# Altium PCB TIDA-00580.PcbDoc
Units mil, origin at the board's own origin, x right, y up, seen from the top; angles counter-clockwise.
Board outline 2640 x 3160 mil, 4 copper layers (Top, Ground, Power, Bottom), stack 38.234 mil thick; 68 components, 61 nets, 219 pads, 95 vias.
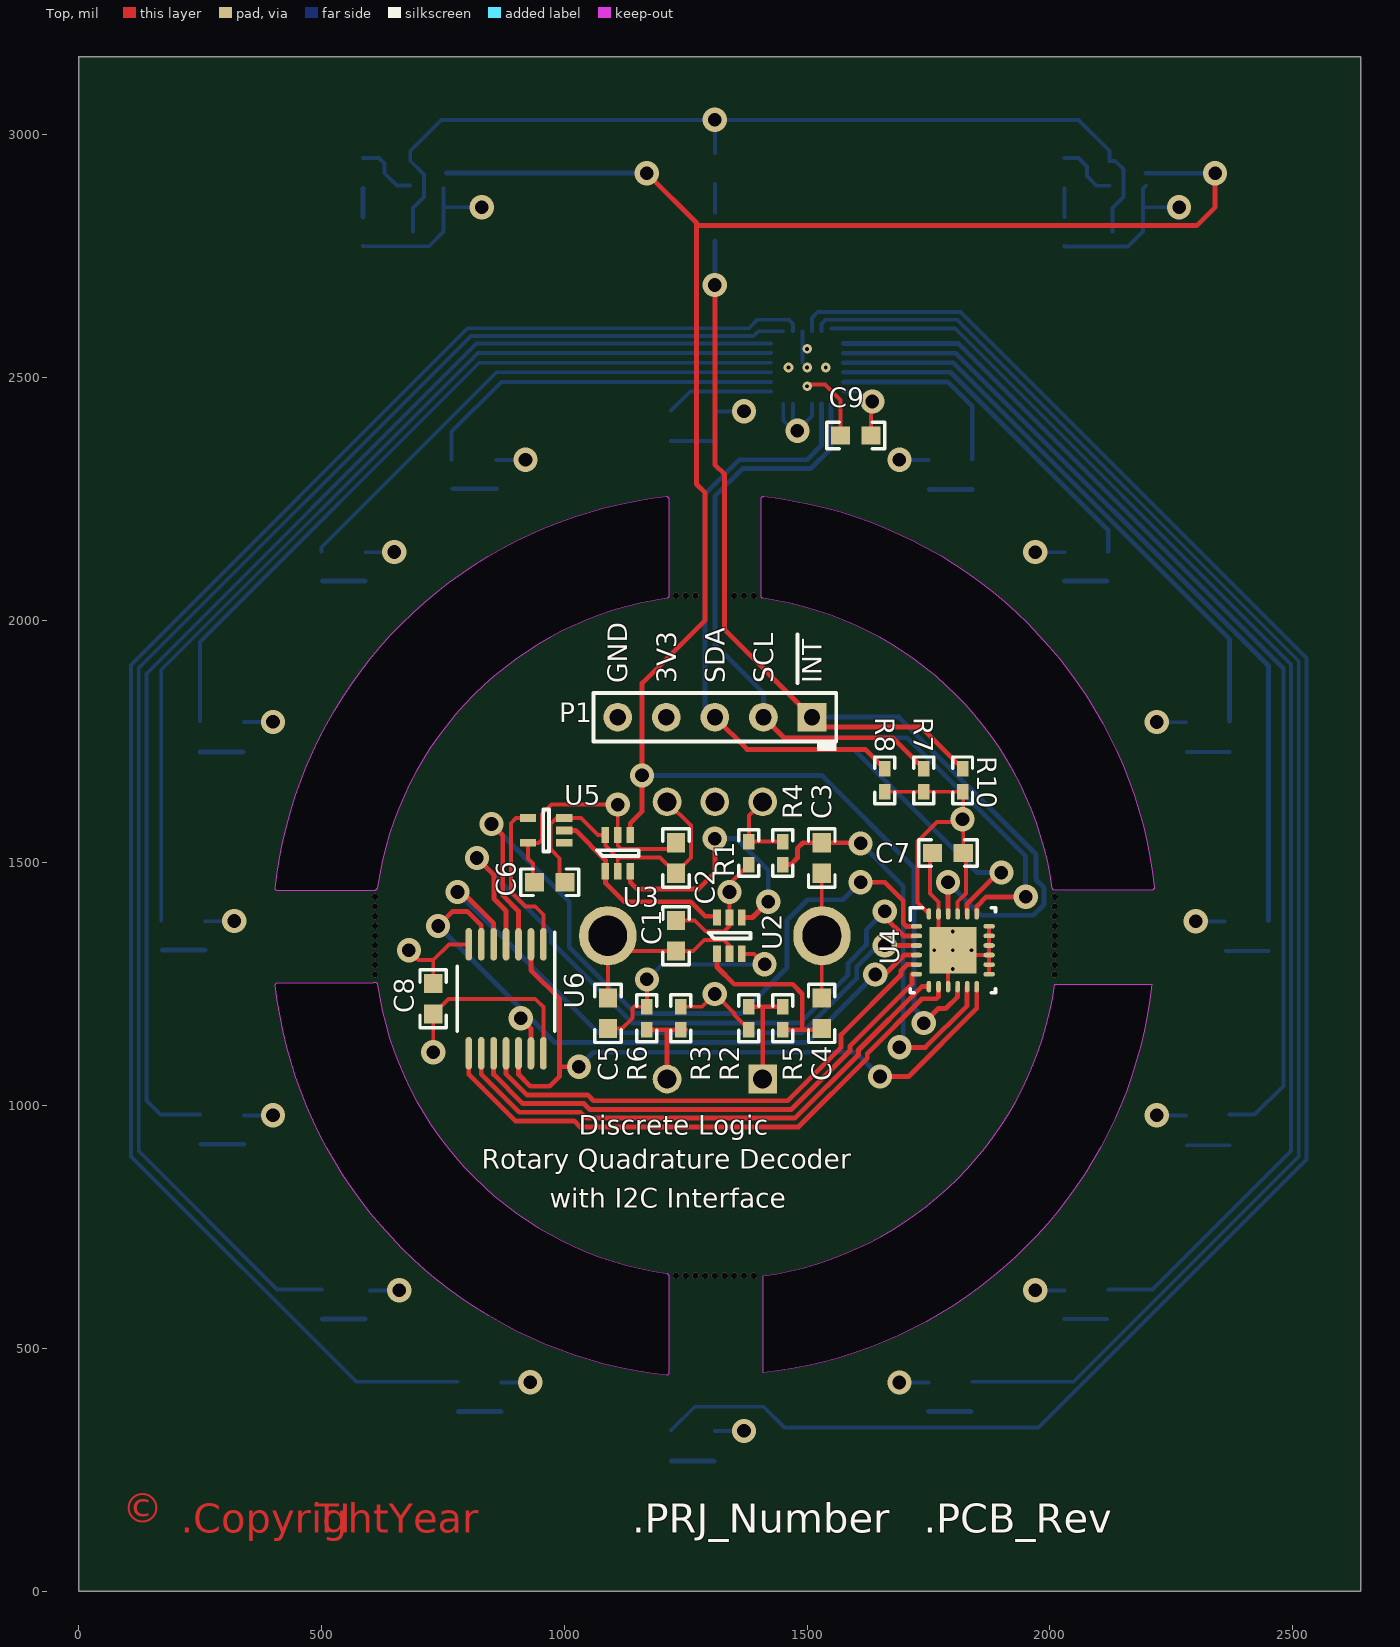
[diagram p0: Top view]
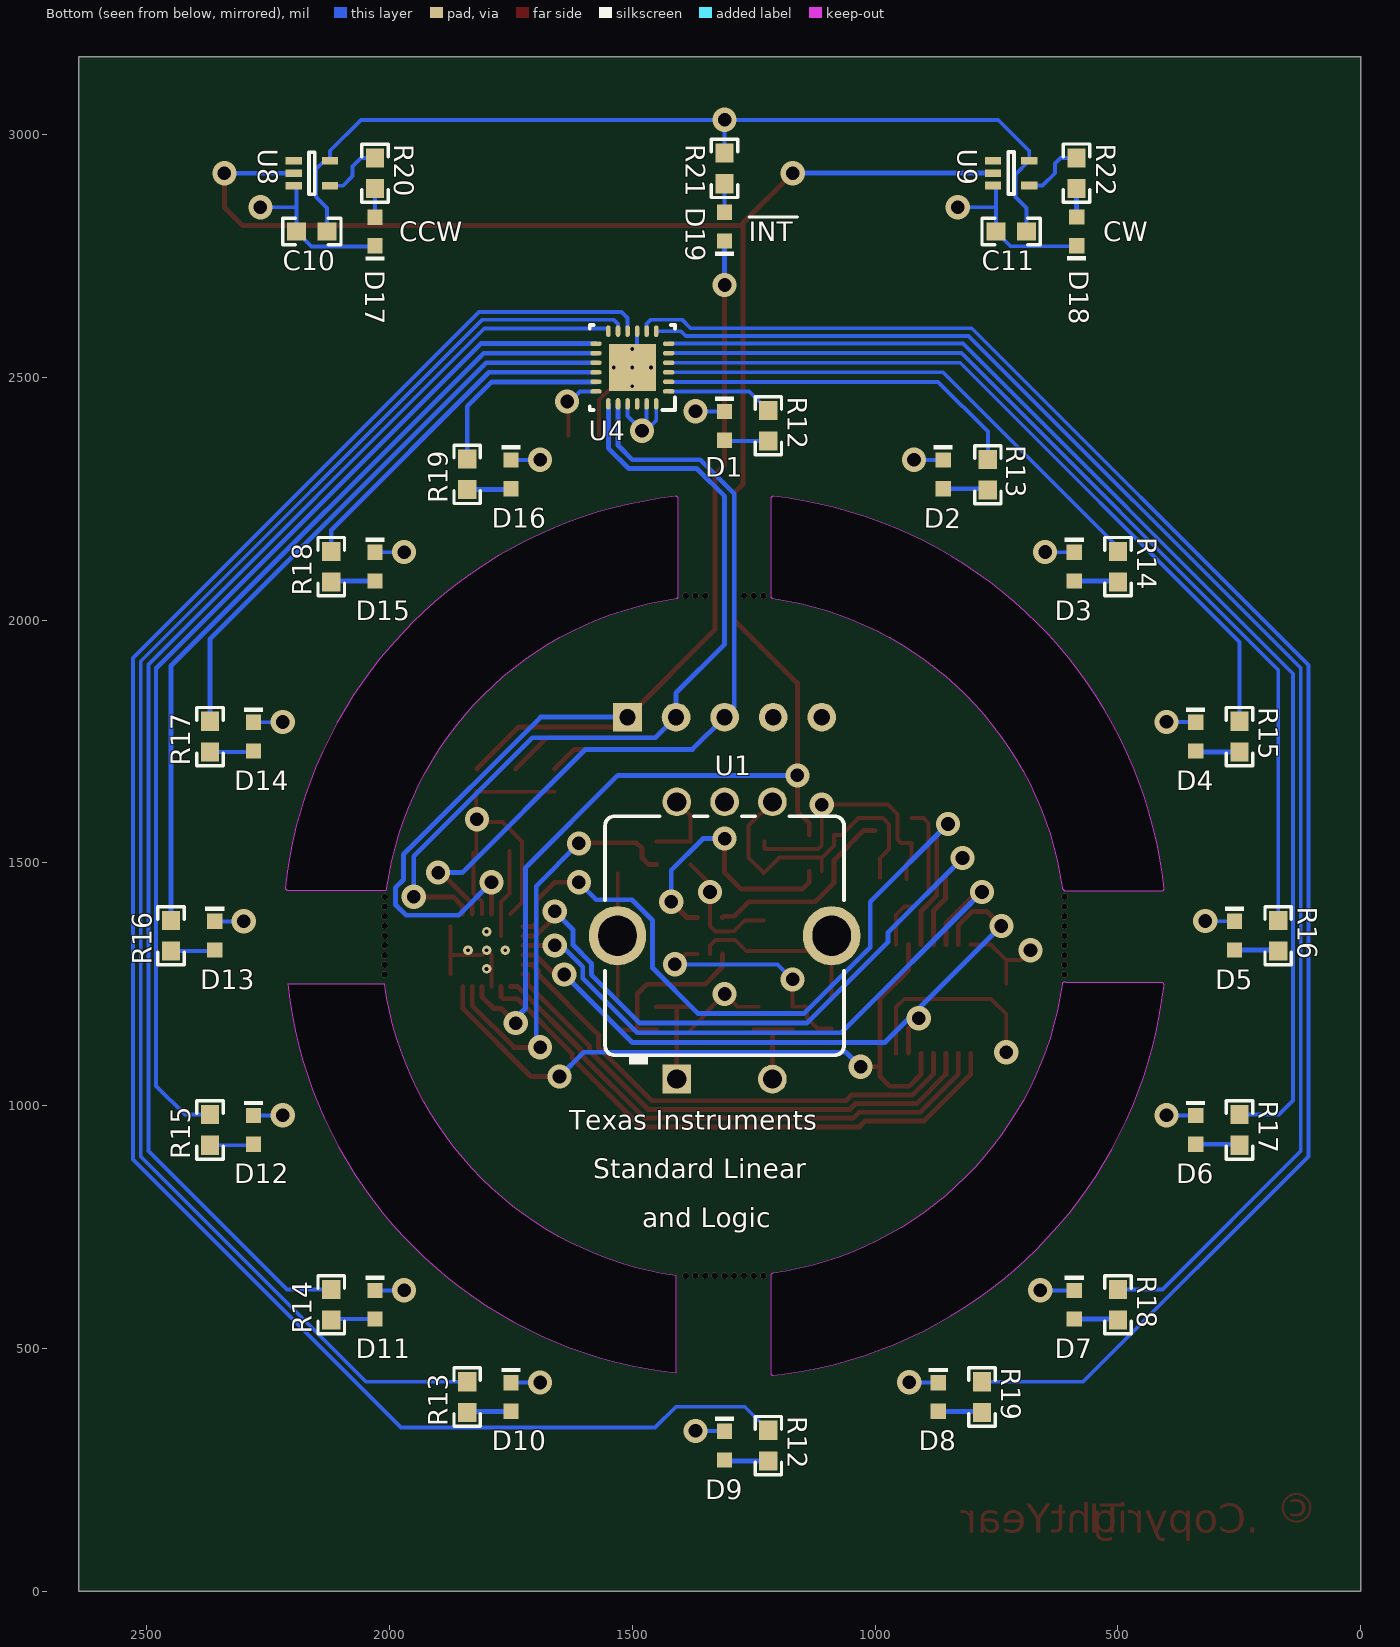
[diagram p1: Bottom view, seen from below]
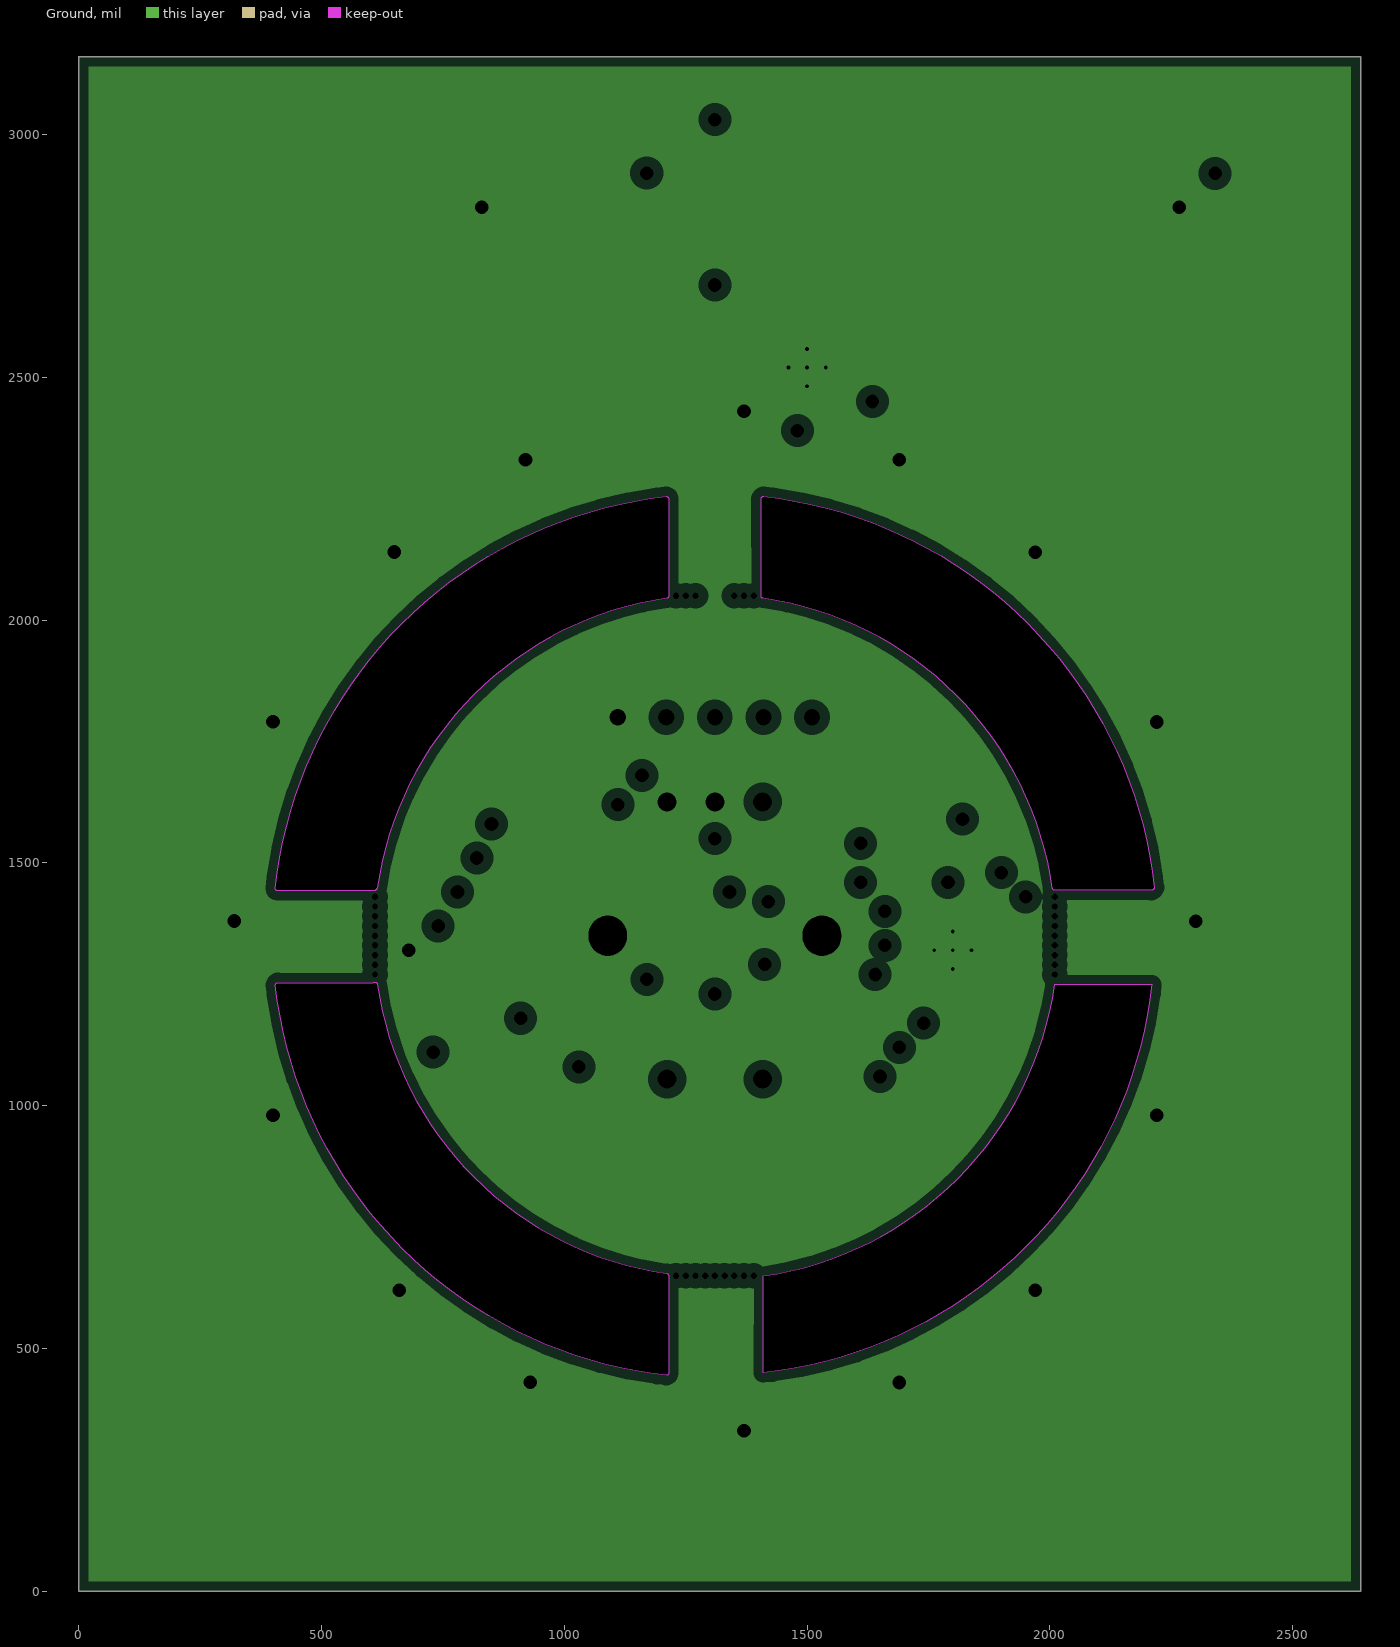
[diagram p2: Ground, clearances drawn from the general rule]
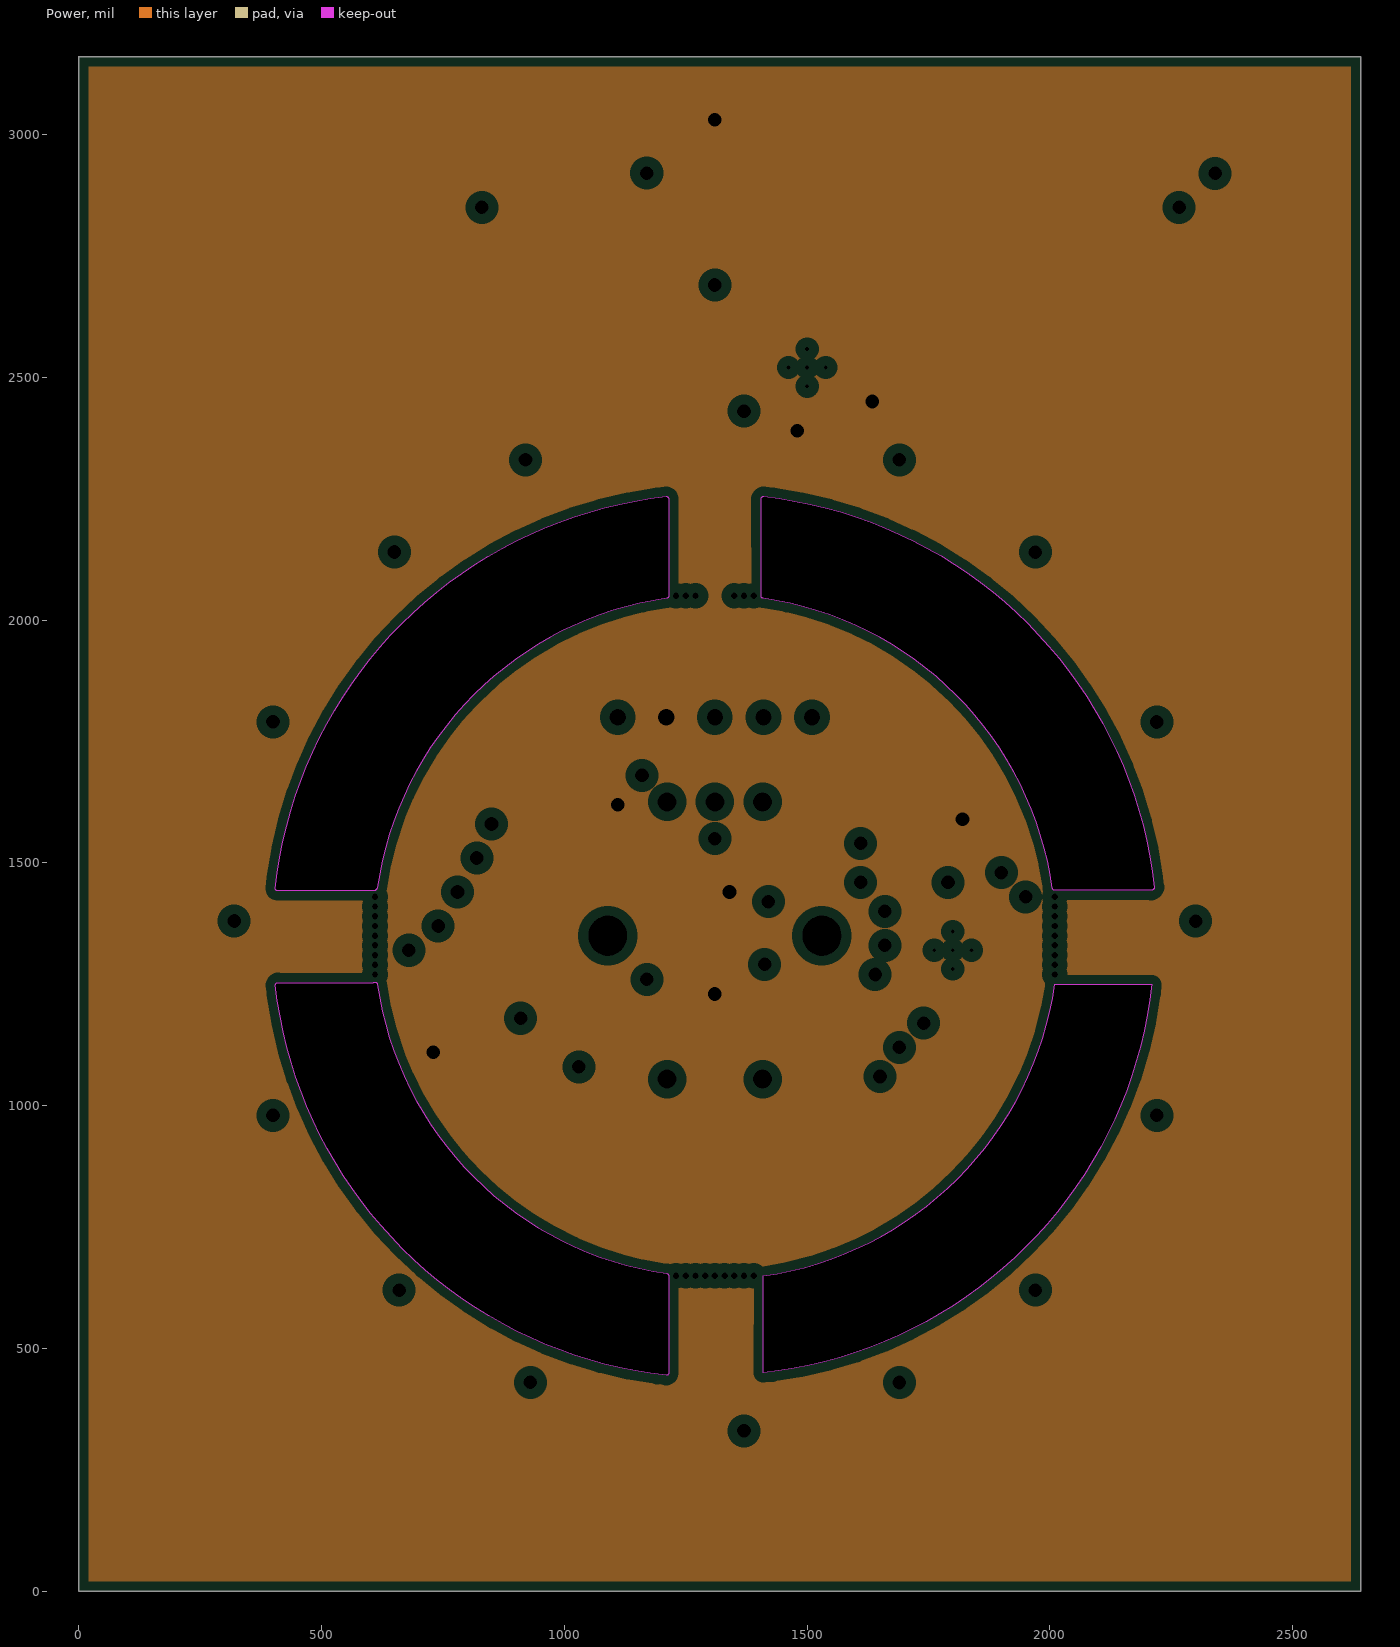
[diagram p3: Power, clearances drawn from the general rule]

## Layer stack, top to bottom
Top Solder: solder mask 0.4, Solder Resist, Dk 3.5
Top: signal copper 1.4
Dielectric 1: core 12.6, FR-4, Dk 4.8
Ground: plane copper 1.417, net GND
Dielectric 3: core 10, Dk 4.2
Power: plane copper 1.417, net 3V3
Dielectric 4: core 10, Dk 4.2
Bottom: signal copper 1.4
Bottom Solder: solder mask 0.4, Solder Resist, Dk 3.5

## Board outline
0,0 0,3160 2640,3160 2640,0 0,0
cut-out: 1409.32,2044.56 cw(c1410,2049.53) 1404.98,2049.53 1404.98,2249.53 cw(c1410,2249.53) 1410.55,2254.52 cw(c1310,1349.53) 2214.98,1450.08 cw(c2210,1449.53) 2215.01,1449.53 cw(c2210,1449.53) 2212.78,1445.36 cw(c2208.62,1448.15) 2208.62,1443.14 2010.19,1443.14 cw(c2010.19,1448.15) 2005.22,1447.48 cw(c1310.2,1349.45) 2005.23,1447.45 2005.22,1447.48 ccw(c1310,1349.53)
cut-out: 409.76,1442.37 cw(c409.76,1447.38) 404.78,1447.92 cw(c1310,1349.53) 1209.44,2254.52 cw(c1210,2249.53) 1215.01,2249.53 1215.01,2049.53 cw(c1210,2049.53) 1210.67,2044.56 cw(c1308.58,1350.43) 1210.71,2044.57 1210.67,2044.56 ccw(c1310,1349.53) 614.96,1448.82 cw(c610,1449.53) 612.3,1445.08 cw(c607.85,1447.38) 607.85,1442.37
cut-out: 405.14,1247.86 cw(c410.12,1248.42) 410.12,1253.44 606.85,1253.44 cw(c610,1249.53) 614.96,1250.24 ccw(c1310,1349.53) 1210.67,654.5 ccw(c1308.58,1348.64) 1210.71,654.5 1210.67,654.5 cw(c1210,649.53) 1215.01,649.53 1215.01,449.53 cw(c1210,449.53) 1209.44,444.55 cw(c1310,1349.53)
cut-out: 1410,449.53 1410,649.53 ccw(c1310,1349.53) 2010,1249.53 2210,1249.53 cw(c1310,1349.53)

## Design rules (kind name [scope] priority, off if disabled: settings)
AcuteAngle [All] p1: minimum=4.50000000000000E+0001 checktracksonly=FALSE
AssemblyTestPointUsage [All] p1: valid=2
Clearance Clearance_Keepouts [((IsTrack Or IsArc) And Not InPoly) And IsFree and IsKeepOut vs ((IsTrack Or IsArc) And Not InPoly) And IsFree and IsKeepOut] p1: gap=0
Clearance Clearance_BoardEdge_MountingHoles [OnCopper and InComponentClass('Mounting Holes') vs IsKeepOut] p2: gap=40
Clearance Clearance_BoardEdge_Poly [OnCopper and InPoly vs IsKeepOut] p3: gap=25
Clearance Clearance_BoardEdge [OnCopper and Not InComponentClass('Logo') and not InComponentClass('FiducialMark') and not InRegion(1000,500,4000,800) and Not IsKeepout vs IsKeepOut] p4: gap=75
Clearance Clearance_Poly [InPolygon] p5: gap=25
Clearance [All] p6: gap=7.87
ComponentClearance ComponentClearance_MountingHoles_FiducialMarks [InComponentClass('Mounting Holes') vs InComponentClass('FiducialMark')] p1: gap=50 collisioncheckmode=3 verticalgap=10 showdistances=FALSE
ComponentClearance ComponentClearance_Shunt [InComponentClass('Header') vs InComponentClass('Shunt')] p2: gap=0 collisioncheckmode=3 verticalgap=0 showdistances=FALSE
ComponentClearance ComponentClearance_Logo [InComponentClass('Logo')] p3: gap=50 collisioncheckmode=3 verticalgap=10 showdistances=FALSE
ComponentClearance ComponentClearance_ScrewToNut [(HasFootprint('NY PMS 440 0025 PH')) vs (HasFootprint('Keystone_1902C'))] p4: gap=5 collisioncheckmode=3 verticalgap=10 showdistances=FALSE
ComponentClearance ComponentClearance_MountingHoles [InComponentClass('Mounting Holes')] p5: gap=250 collisioncheckmode=3 verticalgap=100000 showdistances=FALSE
ComponentClearance ComponentClearance_SmallPassives [HasFootprint('0201*') or HasFootprint('0402*') or HasFootprint('0508') or HasFootprint('0603*') or HasFootprint('0612') or HasFootprint('0805*') or HasFootprint('0815*') or HasFootprint('0830*') or HasFootprint('1206*') or HasFootprint('1210*') or HasFootprint('1808*') or HasFootprint('1812*') or HasFootprint('1825*') or HasFootprint('2010*') or HasFootprint('2220*') or HasFootprint('2225*') or HasFootprint('2512*') or HasFootprint('2728*') or HasFootprint('3518*') vs HasFootprint('0201*') or HasFootprint('0402*') or HasFootprint('0508') or HasFootprint('0603*') or HasFootprint('0612') or HasFootprint('0805*') or HasFootprint('0815*') or HasFootprint('0830*') or HasFootprint('1206*') or HasFootprint('1210*') or HasFootprint('1808*') or HasFootprint('1812*') or HasFootprint('1825*') or HasFootprint('2010*') or HasFootprint('2220*') or HasFootprint('2225*') or HasFootprint('2512*') or HasFootprint('2728*') or HasFootprint('3518*')] p6: gap=20 collisioncheckmode=3 verticalgap=10 showdistances=FALSE
ComponentClearance ComponentClearance_THtoSMT [IsThruComponent vs IsSMTComponent] p7: gap=25 collisioncheckmode=3 verticalgap=30 showdistances=FALSE
ComponentClearance ComponentClearance_THtoTH [IsThruComponent vs IsThruComponent] p8: gap=25 collisioncheckmode=3 verticalgap=30 showdistances=FALSE
ComponentClearance [All] p9: gap=25 collisioncheckmode=3 verticalgap=10 showdistances=FALSE
DiffPairsRouting [All] p1: maxlimit=100 minlimit=10 mostfreqgap=10 toplayer_minwidth=15 toplayer_maxwidth=15 toplayer_prefwidth=15 bottomlayer_minwidth=15 bottomlayer_maxwidth=15 bottomlayer_prefwidth=15 maxuncoupledlength=1000
FabricationTestPointUsage TestPointUsage [All] p1: valid=2 allowmultiple=FALSE
FabricationTestpoint Testpoint [All] p1: side=3 testpointundercomponent=TRUE minsize=40 maxsize=100 preferedsize=60 minholesize=0 maxholesize=40 preferedholesize=32 testpointgrid=1 allowsidetop=TRUE allowsidebottom=TRUE usegrid=TRUE gridtolerance=0.01
FanoutControl Fanout_LCC [IsLCC] p1: bgadir=Out bgaviamode=Centered fanoutstyle=Auto fanoutdirection=Alternating viagrid=1 // Fanout_LCC (Default Rule)
FanoutControl Fanout_BGA [IsBGA] p2: bgadir=Out bgaviamode=Centered fanoutstyle=Auto fanoutdirection=Alternating viagrid=1 // Fanout_BGA (Default Rule)
FanoutControl Fanout_Default [All] p4: bgadir=Out bgaviamode=Centered fanoutstyle=Auto fanoutdirection=Alternating viagrid=1 // Fanout_Default (Default Rule)
FanoutControl Fanout_Small [(CompPinCount < 5)] p5: bgadir=Out bgaviamode=Centered fanoutstyle=Auto fanoutdirection=OutThenIn viagrid=1 // Fanout_Small (Default Rule)
HoleSize [All] p1: absolutevalues=TRUE maxlimit=251 minlimit=8 maxpercent=80.000 minpercent=20.000
MinimumAnnularRing MinimumAnnularRing_ThermalPadVias [IsVia and InAnyComponent] p1: minimumring=5.91
MinimumAnnularRing [All] p2: minimumring=9
MinimumSolderMaskSliver MinimumSolderMaskSliver_Logo [InComponentClass('Logo') vs InComponentClass('Logo')] p1: minsoldermaskwidth=0.7
MinimumSolderMaskSliver [All] p2: minsoldermaskwidth=3.94
PlaneClearance [All] p1: clearance=20
PlaneConnect [All] p1: planeconnectstyle=Relief reliefexpansion=10 reliefentries=4 reliefconductorwidth=10 reliefairgap=10
PolygonConnect [All] p1: connectstyle=Relief reliefconductorwidth=10 reliefentries=4 polygonreliefangle="90 Angle" airgapwidth=10
RoutingVias ThermalPadVias [IsVia and InAnyComponent] p1: holewidth=7.87 width=19.68 viastyle="Through Hole" minholewidth=7.87 minwidth=19.68 maxholewidth=12.99 maxwidth=23.62
RoutingVias [All] p2: holewidth=13 width=34 viastyle="Through Hole" minholewidth=13 minwidth=20 maxholewidth=40 maxwidth=65
SilkToBoardRegionClearance [Not ((IsComment or IsDesignator) And (Hide <> 'False')) and not InRegion(1000,500,4000,800)] p1:
SilkToSilkClearance SilkToSilkClearance_Pb-FreeLogo [(HasFootprint('Pb-Free_Overlay_Medium') OR HasFootprint('Pb-Free_Overlay_Small')) vs (HasFootprint('Pb-Free_Overlay_Medium') OR HasFootprint('Pb-Free_Overlay_Small'))] p1: silktosilkclearance=0
SilkToSilkClearance [All] p2: silktosilkclearance=5
SilkToSolderMaskClearance "Silk to Solder Mask Opening" [All] p1: minsilkscreentomaskgap=1 clearancetoexposedcopper=FALSE
SolderMaskExpansion [All] p1: expansion=1.97
UnpouredPolygon [All] p1: allowunpoured=FALSE
Width [All] p1: maxlimit=100 minlimit=6 preferedwidth=10 checkconnectedcopper=TRUE
13 further rules are at their usual default settings.

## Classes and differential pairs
component class "Test Interface": C9 C10 C11 D1 D2 D3 D4 D5 D6 D7 D8 D9 D10 D11 D12 D13 D14 D15 D16 D17 D18 D19 R12 R13 R14 R15 R16 R17 R18 R19 R20 R21 R22 U4 U8 U9
component class TIDA-00580_Schematic: 3V3 C1 C2 C3 C4 C5 C6 C7 C8 P1 R1 R2 R3 R4 R5 R6 R7 R8 R10 U1 U2 U3 U4 U5 U6
component class Header: P1

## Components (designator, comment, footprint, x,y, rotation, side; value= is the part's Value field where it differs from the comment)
C1 "0603YC104JAT2A" 0603 1230,1350 r270 top
C2 "0603YC104JAT2A" 0603 1230,1510 r270 top
C3 "0603YC104JAT2A" 0603 1530,1510 r270 top
C4 "0603YC104JAT2A" 0603 1530,1190 r90 top
C5 "0603YC104JAT2A" 0603 1090,1190 r90 top
C6 "0603YC104JAT2A" 0603 970,1460 r0 top
C7 "0603YC104JAT2A" 0603 1790,1520 r180 top
C8 "0603YC104JAT2A" 0603 730,1220 r90 top
C9 "0603YC104JAT2A" 0603 1600,2380 r180 top
C10 "0603YC104JAT2A" 0603 2160,2800 r0 bottom
C11 "0603YC104JAT2A" 0603 720,2800.32 r0 bottom
D1 "LB Q39G-L2N2-35-1" "LB Q39G_BLUE" 1310,2400 r90 bottom
D2 "LB Q39G-L2N2-35-1" "LB Q39G_BLUE" 860,2300 r90 bottom
D3 "LB Q39G-L2N2-35-1" "LB Q39G_BLUE" 590,2110 r90 bottom
D4 "LB Q39G-L2N2-35-1" "LB Q39G_BLUE" 340,1760 r90 bottom
D5 "LB Q39G-L2N2-35-1" "LB Q39G_BLUE" 260,1350 r90 bottom
D6 "LB Q39G-L2N2-35-1" "LB Q39G_BLUE" 340,950 r90 bottom
D7 "LB Q39G-L2N2-35-1" "LB Q39G_BLUE" 590,590 r90 bottom
D8 "LB Q39G-L2N2-35-1" "LB Q39G_BLUE" 870,400 r90 bottom
D9 "LB Q39G-L2N2-35-1" "LB Q39G_BLUE" 1310,300 r90 bottom
D10 "LB Q39G-L2N2-35-1" "LB Q39G_BLUE" 1750,400 r90 bottom
D11 "LB Q39G-L2N2-35-1" "LB Q39G_BLUE" 2030,590 r90 bottom
D12 "LB Q39G-L2N2-35-1" "LB Q39G_BLUE" 2280,950 r90 bottom
D13 "LB Q39G-L2N2-35-1" "LB Q39G_BLUE" 2359.99,1350 r90 bottom
D14 "LB Q39G-L2N2-35-1" "LB Q39G_BLUE" 2280,1760 r90 bottom
D15 "LB Q39G-L2N2-35-1" "LB Q39G_BLUE" 2030,2110 r90 bottom
D16 "LB Q39G-L2N2-35-1" "LB Q39G_BLUE" 1750,2300 r90 bottom
D17 "LB Q39G-L2N2-35-1" "LB Q39G_BLUE" 2030,2800 r270 bottom
D18 "LB Q39G-L2N2-35-1" "LB Q39G_BLUE" 585.11,2800.32 r270 bottom
D19 "LB Q39G-L2N2-35-1" "LB Q39G_BLUE" 1310,2810 r270 bottom
P1 "800-10-005-10-001000" Mill-Max_800-10-005-10-001000 1310,1800 r180 top
R1 "CRCW04021K00FKED" 0402 1380,1520 r270 top
R2 "CRCW04021K00FKED" 0402 1380,1180 r270 top
R3 "CRCW04021K00FKED" 0402 1240,1180 r90 top
R4 "CRCW04021K00FKED" 0402 1450,1520 r90 top
R5 "CRCW04021K00FKED" 0402 1450,1180 r90 top
R6 "CRCW04021K00FKED" 0402 1170,1180 r270 top
R7 "CRCW04024K70JNED" 0402 1740,1670 r270 top
R8 "CRCW04024K70JNED" 0402 1660,1670 r270 top
R10 "CRCW040210K0JNED" 0402 1820,1670 r270 top
R12 "CRCW0603100RJNEA" 0603 1220,300 r90 bottom
R12 "CRCW0603100RJNEA" 0603 1220,2400 r90 bottom
R13 "CRCW0603100RJNEA" 0603 1840,400 r90 bottom
R13 "CRCW0603100RJNEA" 0603 767.95,2299.1 r90 bottom
R14 "CRCW0603100RJNEA" 0603 2120,590 r90 bottom
R14 "CRCW0603100RJNEA" 0603 500,2110 r90 bottom
R15 "CRCW0603100RJNEA" 0603 2370,950 r90 bottom
R15 "CRCW0603100RJNEA" 0603 250,1760 r90 bottom
R16 "CRCW0603100RJNEA" 0603 2450,1350 r90 bottom
R16 "CRCW0603100RJNEA" 0603 170,1350 r90 bottom
R17 "CRCW0603100RJNEA" 0603 2370,1760 r90 bottom
R17 "CRCW0603100RJNEA" 0603 250,950 r90 bottom
R18 "CRCW0603100RJNEA" 0603 2120,2110 r90 bottom
R18 "CRCW0603100RJNEA" 0603 500,590 r90 bottom
R19 "CRCW0603100RJNEA" 0603 1840,2300 r90 bottom
R19 "CRCW0603100RJNEA" 0603 780,400 r90 bottom
R20 "CRCW0603100RJNEA" 0603 2030,2920 r90 bottom
R21 "CRCW0603100RJNEA" 0603 1310,2930 r90 bottom
R22 "CRCW0603100RJNEA" 0603 585.11,2920.32 r90 bottom
U1 "EVE-JBBF2020B" Panasonic_EVE-JBBF2020B 1310,1350 r90 bottom
U2 "SN74LVC2G17QDCKRQ1" DCK0006A_N 1340,1350 r90 top
U3 "SN74LVC1G374DCKR" DCK0006A_N 1110,1520 r90 top
U4 "TCA9539RTWR" RTW0024B 1800,1320 r0 top
U4 "TCA9539RTWR" RTW0024B 1500,2520 r0 bottom
U5 "SN74LVC1G04QDCKRQ1" DCK0005A_N 962.4,1566.73 r180 top
U6 "SN74LV393ATPWRQ1" PW0014A_N 880,1220 r270 top
U8 "SN74LV1T34DCKR" DCK0005A_N 2160,2920 r180 bottom
U9 "SN74LV1T04DCK" DCK0005A_N 720,2920.32 r180 bottom

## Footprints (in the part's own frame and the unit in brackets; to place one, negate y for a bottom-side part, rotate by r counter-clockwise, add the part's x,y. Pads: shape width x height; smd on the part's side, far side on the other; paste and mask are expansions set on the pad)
0402 [mm] "0402 from SM-752 data"
  rect 0.8x0.6 smd: 1(-0.6,0) 2(0.6,0)
  silkscreen extent -1.22,-0.52 1.22,0.52, body extent -0.55,-0.3 0.55,0.3, height 0.6
0603 [mm] "0603 from SM-752 data"
  rect 1x0.95 smd: 1(-0.8,0) 2(0.8,0)
  silkscreen extent -1.52,-0.69 1.52,0.69, body extent -0.87,-0.47 0.87,0.47, height 0.85
DCK0005A_N [mm] "SOT353, 5-Leads, Body 2x1.3mm, Pitch 0.65mm, Lead Span 2.1mm, IPC Medium Density"
  rect 0.85x0.4 smd: 1(-0.95,0.65) 2(-0.95,0) 3(-0.95,-0.65) 4(0.95,-0.65) 5(0.95,0.65)
  silkscreen extent -0.15,-1.1 0.15,1.1, body extent -1.14,-1 1.14,1, height 0.94
DCK0006A_N [mm] "SOT23, 6-Leads, Body 2x1.3mm, Pitch 0.65mm, Lead Span 2.1mm, IPC Medium Density"
  rect 0.85x0.4 smd: 1(-0.95,0.65) 2(-0.95,0) 3(-0.95,-0.65) 4(0.95,-0.65) 5(0.95,0) 6(0.95,0.65)
  silkscreen extent -0.15,-1.1 0.15,1.1, body extent -1.14,-1 1.14,1, height 0.94
"LB Q39G_BLUE" [mm] "OSRAM"
  rect 0.8x0.8 smd: 1(-0.75,0) 2(0.75,0)
  silkscreen extent 1.3,-0.5 1.52,0.5, body extent -0.85,-0.45 0.85,0.45, height 0.4
Mill-Max_800-10-005-10-001000 [mm] "Mill-Max"
  rect 1.5x1.5 hole 0.85: 1(-5.08,0)
  round 1.5 hole 0.85: 2(-2.54,0) 3(0,0) 4(2.54,0) 5(5.08,0)
  silkscreen extent -6.35,-1.27 6.35,1.78, body extent -6.35,-1.27 6.35,1.27, height 8.13
Panasonic_EVE-JBBF2020B [mm] "TH, 5-Leads, Body 12.4x12.4mm, Pitch 2.5mm"
  rect 1.5x1.5 hole 1: 1(-7.5,2.5)
  round 1.5 hole 1: 2(-7.5,-2.5) 3(7,2.5) 4(7,0) 5(7,-2.5)
  oval 3.1x3 hole 2 slot 2.1 at 0 deg: 6(0,5.6) 7(0,-5.6)
  silkscreen extent -6.75,-6.25 6.25,6.25, body extent -7.6,-6.7 7.1,6.7, height 20.1
PW0014A_N [mm] "TSOP, 14-Leads, Body 5x4.4mm, Pitch 0.65mm, IPC Medium Density"
  oval 1.7x0.35 smd: 1(-2.85,1.95) 2(-2.85,1.3) 3(-2.85,0.65) 4(-2.85,0) 5(-2.85,-0.65) 6(-2.85,-1.3) 7(-2.85,-1.95) 8(2.85,-1.95) 9(2.85,-1.3) 10(2.85,-0.65) 11(2.85,0) 12(2.85,0.65) 13(2.85,1.3) 14(2.85,1.95)
  silkscreen extent -3.47,-2.55 1.7,2.55, body extent -3.21,-2.5 3.21,2.5, height 0.98
RTW0024B [mm] "QFN, 24-Leads, Body 4x4mm, Pitch 0.5mm, Thermal Pad 2.45x2.45mm, TI Recommended"
  oval 0.6x0.24 smd: 1(-1.9,1.25) 2(-1.9,0.75) 3(-1.9,0.25) 4(-1.9,-0.25) 5(-1.9,-0.75) 6(-1.9,-1.25) 13(1.9,-1.25) 14(1.9,-0.75) 15(1.9,-0.25) 16(1.9,0.25) 17(1.9,0.75) 18(1.9,1.25)
  oval 0.24x0.6 smd: 7(-1.25,-1.9) 8(-0.75,-1.9) 9(-0.25,-1.9) 10(0.25,-1.9) 11(0.75,-1.9) 12(1.25,-1.9) 19(1.25,1.9) 20(0.75,1.9) 21(0.25,1.9) 22(-0.25,1.9) 23(-0.75,1.9) 24(-1.25,1.9)
  rect 2.45x2.45 smd paste-1.225: 25(0,0)
  silkscreen extent -2.22,-2.22 2.22,2.22, body extent -2.07,-2.07 2.07,2.07, height 0.81

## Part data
C1 C2 C3 C4 C5 C6 C7 C8 C9 C10 C11: "CAP, CERM, 0.1 µF, 16 V, +/- 5%, X7R, 0603"
D1 D2 D3 D4 D5 D6 D7 D8 D9 D10 D11 D12 D13 D14 D15 D16 D17 D18 D19: "LED, Blue, SMD"
P1: "Header, 100mil, 5x1, TH"
R1 R2 R3 R4 R5 R6: "RES, 1.00 k, 1%, 0.063 W, 0402"
R7 R8: "RES, 4.7 k, 5%, 0.063 W, 0402"
R10: "RES, 10 k, 5%, 0.063 W, 0402"
R12 R12 R13 R13 R14 R14 R15 R15 R16 R16 R17 R17 R18 R18 R19 R19 R20 R21 R22: "RES, 100, 5%, 0.1 W, 0603"
U1: "ENCODER ROTARY 12MM 20PPR W/SW, TH"
U2: "Dual Schmitt Trigger Buffer, DCK0006A"
U3: "Single D-Type Flip-Flop With 3-State Output, DCK0006A"
U4 U4: "Remote 16-Bit I2C and SMBus, Low-Power I/O Expander with Interrupt Output, Reset & Config. Register, 1.65 to 5.5 V, -40 to 85 degC, 24-pin QFN (RTW), Green (RoHS & no Sb/Br)"
U5: library part SN74LVC1G04DCKR, "Single Inverter Gate, DCK0005A"
U6: "DUAL 4-BIT BINARY COUNTER, PW0014A"
U8: "Single Power Supply Single Buffer GATE CMOS Logic Level Shifter, DCK0005A"
U9: "SN74LV1T04 Single Power Supply Inverter Gate CMOS Logic Level Shifter, DCK0005A"

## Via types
v1: diameter 50, hole 28, Top to Bottom, 52 vias
v2: diameter 13, hole 13, Top to Bottom, 33 vias
v3: diameter 19.68, hole 7.87, Top to Bottom, 10 vias

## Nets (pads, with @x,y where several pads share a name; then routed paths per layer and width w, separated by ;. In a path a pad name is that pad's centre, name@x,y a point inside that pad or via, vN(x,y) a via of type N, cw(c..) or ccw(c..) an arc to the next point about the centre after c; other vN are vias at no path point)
3V3: C1.1 C2.1 C6.1 C7.1 C8.1 C9.1 C10.1 C11.1 P1.4 R1.2 R2.2 R3.2 R7.2 R8.2 R10.2 R21.2 U2.5 U3.5 U4.18@1574.8,2470.79 U4.21 U4.23@1470.47,2445.2 U4.24 U5.5 U6.14 U8.5 U9.5 | length 4368.6
  Top w8: v1(730,1110) C8.1 761.5,1220 940,1220 956.77,1203.23 U6.14 ; C6.1@935.57,1466.73 935.57,1498.76 925,1509.33 U5.5 946.81,1541.14 953.61,1547.94 953.61,1600 973.61,1620 v1(1110,1620) U3.5 1110,1535.91 1117.11,1528.8 1227.16,1528.8 1227.5,1529.13 C2.1@1227.5,1544 ; C1.1 1268.5,1381.5 1290.92,1359.08 1300,1359.08 1300.28,1358.8 1329.11,1358.8 1340,1369.69 U2.5 1340,1456.38 R1.2 ; R3.2 1283.62,1203.62 v1(1310,1230) 1350,1190 1350,1186.38 R2.2 ; C9.1 v1@1631.5,2447.08 ; R8.2 R10.2 ; U4.24@1750.79,1394.8 1726.95,1418.65 1726.95,1543.62 1767.58,1584.25 v1@1821.5,1584.25 ; U4.21@1809.84,1394.8 1809.84,1419.84 1826.87,1436.87 C7.1@1826.87,1520 ; C7.1 v1@1821.5,1584.25 ; R10.2@1821.5,1648.5 v1@1821.5,1584.25
  Bottom w8: C11.1 688.5,2848.82 711.2,2871.52 711.2,2917.3 U9.5 682.6,2966.06 746.54,3030 v1@1310,3030 ; v1@1305.91,3030 2059.06,3030 2122.6,2966.46 U8.5 2134.41,2945.59 2151.2,2928.8 2151.2,2871.21 2128.5,2848.5 C10.1 ; R21.2 v1(1310,3030.47) ; U4.24@1450.79,2445.2 1450.79,2410.79 v1@1471.57,2390 ; v1@1470.47,2399.53 U4.23@1470.47,2445.2 ; v1(1480,2390) 1509.84,2419.84 U4.21@1509.84,2445.2 ; U4.18@1574.8,2470.79 1608.05,2470.79 1628.84,2450 v1(1634.42,2450)
  other v1: 1340,1440 1820,1590
\INT\: D19.2 P1.1 R10.1 U4.22@1790.16,1394.8 | length 2406.2
  Top w10: v1(1310,2690) 1310,2320 1330,2300 1330,1980 P1.1 1530,1780 1733.62,1780 R10.1 ; v1(1790,1460) 1790,1394.96 U4.22@1790.16,1394.8
  Bottom w10: v1(1310,2690) D19.2 ; P1.1 1688.84,1800 1971.2,1517.64 1971.2,1465.49 1987.87,1448.82 1987.87,1414.31 1965.69,1392.13 1857.87,1392.13 v1(1790,1460)
A: C4.1 R5.1 U2.1 | length 377.1
  Top w10: U2.1 1314.41,1285.59 1350,1250 1470,1250 1490,1230 1490,1156.38 ; R5.1 1490,1156.38 ; C4.1@1527.87,1156.38 1490,1156.38
A_BUF: U2.6 U3.1 U5.2 | length 416.3
  Top w10: U5.2 1023.27,1566.73 1084.41,1505.59 U3.1 1084.41,1458.81 1123.22,1420 1260,1420 1290,1390 1311.81,1390 U2.6
A_NOT: U5.4 U6.1 | length 328.2
  Top w8: U5.4 900.75,1592.32 890,1581.58 890,1440 920,1410 940,1410 956.77,1393.23 U6.1
B: C5.1 R6.1 U2.3 | length 478.7
  Top w8: C5.1 1118.5,1158.5 1140,1180 1140,1200 1145,1205 1146.38,1203.62 R6.1 v1(1170,1260) ; U2.3 1390.63,1312.6 v1(1412.29,1290.95)
  Bottom w8: v1(1170,1260) 1200.94,1290.95 v1(1412.29,1290.95)
B_BUF: U2.4 U3.3 | length 556.2
  Top w10: U3.3 1135.59,1460.43 1150.08,1445.95 1275.94,1445.95 1310,1480 v1(1310,1550) ; U2.4 1387.4,1387.4 v1(1420,1420)
  Bottom w10: v1(1310,1550) 1354.5,1550 1420,1484.5 v1(1420,1420)
COUNT0: U4.1@1725.2,1369.21 U6.3 | length 1596.8
  Top w10: v1(850,1580) 873.13,1556.87 873.13,1433.01 905.59,1400.55 U6.3 ; v1(1610,1460) 1660,1460 1697.87,1422.13 1697.87,1375.7 1704.36,1369.21 U4.1@1725.2,1369.21
  Bottom w10: v1(850,1580) 1010,1420 1010,1325.84 1145.84,1190 1364.9,1190 1458.54,1283.64 1458.54,1381.76 1500.68,1423.9 1573.9,1423.9 v1(1610,1460)
COUNT1: U4.2@1725.2,1349.53 U6.4 | length 1415.2
  Top w10: v1(820,1510) 855.25,1474.75 855.25,1425.61 880,1400.86 U6.4 ; v1(1660,1400) 1660,1388.29 1698.77,1349.53 U4.2@1725.2,1349.53
  Bottom w10: v1(820,1510) 973.19,1356.81 973.19,1337.37 1140.56,1170 1484.72,1170 1584.25,1269.53 1584.25,1293.09 1622.13,1330.97 1622.13,1362.13 v1(1660,1400)
COUNT2: U4.3@1725.2,1329.84 U6.5 | length 1274.7
  Top w10: v1@790,1440 854.41,1375.59 U6.5 ; v1(1660,1330) 1725.04,1330 U4.3@1725.2,1329.84
  Bottom w10: v1(780,1440) 1070,1150 1490,1150 1602.13,1262.13 1602.13,1285.69 v1@1646.44,1330
COUNT3: U4.4@1725.2,1310.16 U6.6 U6.13 | length 1392.4
  Top w10: v1(740,1370) 770,1400 800,1400 828.82,1371.18 U6.6 ; v1(910,1180) 931.18,1158.82 U6.13 ; v1(1640,1270) 1660,1270 1700.16,1310.16 U4.4@1725.2,1310.16
  Bottom w10: v1(740,1370) 980,1130 1500,1130 v1(1640,1270)
COUNT4: U4.5@1725.2,1290.47 U6.11 | length 1047.5
  Top w10: U6.11 880,1064.72 922.6,1022.13 1047.87,1022.13 1060,1010 1460,1010 1570,1120 1570,1146.44 1693.56,1270 1693.56,1278.28 1705.75,1290.47 U4.5@1725.2,1290.47
COUNT5: U4.6@1725.2,1270.79 U6.10 | length 1077.3
  Top w10: U6.10 854.41,1064.41 914.56,1004.25 1040.47,1004.25 1052.6,992.13 1467.4,992.13 1587.87,1112.6 1587.87,1121.99 1715.75,1249.87 1715.75,1270.79 U4.6@1725.2,1270.79
COUNT6: U4.7@1750.79,1245.2 U6.9 | length 1120.2
  Top w10: U6.9 828.82,1064.72 907.16,986.38 1033.07,986.38 1045.19,974.25 1474.81,974.25 1605.75,1105.19 1605.75,1114.59 1736.36,1245.2 U4.7@1750.79,1245.2
COUNT7: U4.8@1770.47,1245.2 U6.8 | length 1192.7
  Top w10: U6.8 803.23,1064.41 899.13,968.5 1020,968.5 1032.13,956.38 1482.21,956.38 1623.62,1097.79 1623.62,1107.18 1736.44,1220 1766.11,1220 1770.47,1224.36 U4.8@1770.47,1245.2
DIR: U3.4 U4.10@1809.84,1245.2 U8.2 U9.2 | length 4260.1
  Top w10: U3.4 1135.59,1581.65 1160,1606.06 v1(1160,1680) 1160,1870 1290,2000 1290,2262.13 1272.13,2280 1272.13,2817.87 v1(1169.69,2920.32) ; 1277.87,2812.13 2302.13,2812.13 2340,2850 v1(2340,2920) ; v1(1740,1170) 1770,1200 1785.48,1200 1809.84,1224.36 U4.10@1809.84,1245.2
  Bottom w10: U9.2 v1(1169.69,2920.32) ; v1(1160,1680) 1530,1680 1720,1490 1720,1200 v1@1747.4,1172.6 ; U8.2 v1(2340,2920)
GND: C1.2 C2.2 C3.2 C4.2 C5.2 C6.2 C7.2 C8.2 C9.2 C10.2 C11.2 D1.2 D2.2 D3.2 D4.2 D5.2 D6.2 D7.2 D8.2 D9.2 D10.2 D11.2 D12.2 D13.2 D14.2 D15.2 D16.2 D17.2 D18.2 P1.5 U1.4 U1.5 U1.6 U1.7 U2.2 U3.2 U3.6 U4.9 U4.13@1874.8,1270.79 U4.14@1874.8,1290.47 U4.15@1874.8,1310.16 U4.16@1874.8,1329.84 U4.17@1874.8,1349.53 U4.18@1874.8,1369.21 U4.23@1770.47,1394.8 U4.25 U5.3 U6.7 U8.3 U9.3 | length 3768.3
  Top w8: v1(680,1320) 700,1300 730,1300 ; C8.2 730,1300 ; U6.7 762.2,1332.2 730,1300 ; C6.2@990,1469.43 990,1509.55 971.2,1528.35 971.2,1553.93 971.2,1579.53 983.99,1592.32 U5.3 1034.53,1592.32 1069.45,1557.4 U3.6 U3.6@1084.41,1546.5 ; U3.6@1083.5,1545.59 U3.6@1084.41,1546.5 ; U1.7 1090,1349.53 C5.2 ; U3.2 1110,1510 ; U1.7@1121.02,1318.5 C1.2 1265.35,1318.5 1288.06,1341.2 1328.8,1341.2 1340,1330 U2.2 ; U1.5 1260.57,1576.59 1260.57,1510.57 1230,1480 C2.2 1197.3,1511.2 1111.2,1511.2 1110,1510 ; v3@1503.37,2484.99 1537,2484.99 1568.5,2453.48 C9.2 ; C4.2 C3.2 ; C7.2@1753.13,1524.62 1753.13,1436.87 1770.47,1419.53 1770.47,1394.8 U4.25@1770.47,1349.53 ; U4.9@1790.16,1245.2 1790.16,1310.16 v3(1800,1320) ; U4.25@1809.84,1310.16 U4.15@1874.8,1310.16 ; U4.13@1874.8,1270.79 1874.8,1290.47 U4.15@1874.8,1310.16 ; U4.18@1874.8,1369.21 1874.8,1349.53 1874.8,1329.84 U4.15@1874.8,1310.16 ; U3.6@1084.41,1546.5 1084.41,1535.59 1110,1510
  Bottom w8: D5.2@260,1379.69 v1@319.53,1379.69 ; D6.2@340,979.69 v1@399.53,979.69 ; D4.2@340,1789.69 v1@399.53,1789.69 ; D18.2 585.11,2769.74 720.92,2769.74 C11.2 751.5,2850 ; D3.2@590,2139.69 v1@649.53,2139.69 ; D7.2@600,619.69 v1@659.53,619.69 ; U9.3@751.5,2888.82 751.5,2850 ; v1(830,2850) 751.5,2850 ; D2.2 v1@919.53,2329.53 ; D8.2@870,429.69 v1@929.53,429.69 ; D9.2@1310,329.69 v1@1369.53,329.69 ; D1.2 v1@1369.53,2429.53 ; U4.25@1490.16,2529.84 U4.9@1490.16,2594.8 ; v1@1690.47,429.53 D10.2 ; v1@1690.47,2329.53 D16.2 ; v1@1970.47,619.53 D11.2 ; v1@1970.47,2139.53 D15.2 ; D17.2 2030,2769.43 2160.92,2769.43 C10.2 2191.5,2850 ; U8.3 2191.5,2888.5 2191.5,2850 ; v1@2220.47,979.53 D12.2 ; v1@2220.47,1789.53 D14.2 ; v1(2265.91,2850) 2191.5,2850 ; v1@2300.47,1379.53 D13.2
  other v1: 1370,330.16 930,430.16 1690,430 660,620.16 1970,620 400,980.16 2220,980 320,1380.16 2300,1380 400,1790.16 2220,1790 650,2140.16 1970,2140 920,2330 1690,2330 1370,2430
  other v3: 1800,1281.61 1761.61,1320 1838.39,1320 1800,1358.39 1500,2481.61 1461.61,2520 1500,2520 1538.39,2520 1500,2558.39
NetD1_1: D1.1 R12.1@1220,2368.5 | length 88
  Bottom w8: R12.1@1220,2368.5 D1.1@1308.03,2368.5
NetD2_1: D2.1 R13.1@767.95,2267.6 | length 89.2
  Bottom w10: R13.1@770.82,2270.47 D2.1
NetD3_1: D3.1 R14.1@500,2078.5 | length 88
  Bottom w10: R14.1@501.97,2080.47 D3.1
NetD4_1: D4.1 R15.1@250,1728.5 | length 88
  Bottom w10: R15.1@250,1728.5 D4.1@338.03,1728.5
NetD5_1: D5.1 R16.1@170,1318.5 | length 88
  Bottom w10: R16.1@171.97,1320.47 D5.1
NetD6_1: D6.1 R17.1@250,918.5 | length 88
  Bottom w10: R17.1@251.97,920.47 D6.1
NetD7_1: D7.1 R18.1@500,558.5 | length 88
  Bottom w10: R18.1@501.97,560.47 D7.1
NetD8_1: D8.1 R19.1@780,368.5 | length 88
  Bottom w10: R19.1@781.97,370.47 D8.1
NetD9_1: D9.1 R12.1@1220,268.5 | length 88
  Bottom w10: R12.1@1220,268.5 D9.1@1308.03,268.5
NetD10_1: D10.1 R13.1@1840,368.5 | length 88
  Bottom w10: D10.1 R13.1@1838.03,370.47
NetD11_1: D11.1 R14.1@2120,558.5 | length 88
  Bottom w8: D11.1 R14.1@2118.03,560.47
NetD12_1: D12.1 R15.1@2370,918.5 | length 88
  Bottom w8: D12.1@2281.97,918.5 R15.1@2370,918.5
NetD13_1: D13.1 R16.1@2450,1318.5 | length 88
  Bottom w8: D13.1@2361.96,1318.5 R16.1@2450,1318.5
NetD14_1: D14.1 R17.1@2370,1728.5 | length 88
  Bottom w8: D14.1@2281.97,1728.5 R17.1@2370,1728.5
NetD15_1: D15.1 R18.1@2120,2078.5 | length 88
  Bottom w10: D15.1 R18.1@2118.03,2080.47
NetD16_1: D16.1 R19.1@1840,2268.5 | length 88
  Bottom w10: D16.1@1751.97,2268.5 R19.1@1840,2268.5
NetD17_1: D17.1 R20.1 | length 59
  Bottom w8: D17.1 R20.1
NetD18_1: D18.1 R22.1 | length 59
  Bottom w10: D18.1 R22.1
NetD19_1: D19.1 R21.1 | length 59
  Bottom w8: D19.1 R21.1
NetR1_1: R1.1 R4.2 U1.3 | length 163.7
  Top w8: U1.3 1380,1597.17 R1.1 R4.2
NetR2_1: R2.1 R5.2 U1.1 | length 218.9
  Top w10: R2.1 1408.43,1203.62 ; U1.1 1408.43,1203.62 ; R5.2 1408.43,1203.62
NetR3_1: R3.1 R6.2 U1.2 | length 180.1
  Top w10: R6.2 R3.1@1250,1156.38 ; U1.2 1211.57,1154.8
NetR20_2: R20.2 U8.4 | length 128
  Bottom w8: R20.2 2058.5,2951.5 2075.91,2934.09 2075.91,2914.09 2095.59,2894.41 U8.4
NetR22_2: R22.2 U9.4 | length 132.8
  Bottom w8: R22.2 618.19,2951.81 630,2940 630,2920 655.28,2894.72 U9.4
OUT1: R12.2@1220,2431.5 U4.1@1425.2,2470.79 | length 221.5
  Bottom w8: R12.2@1220,2431.5 1259.29,2470.79 U4.1@1425.2,2470.79
OUT2: R13.2@767.95,2330.59 U4.2@1425.2,2490.47 | length 757.1
  Bottom w8: R13.2@767.95,2330.59 767.95,2387.95 870.47,2490.47 U4.2@1425.2,2490.47
OUT3: R14.2@500,2141.5 U4.3@1425.2,2510.16 | length 1082.9
  Bottom w8: R14.2@500,2141.5 500,2150 860.16,2510.16 U4.3@1425.2,2510.16
OUT4: R15.2@250,1791.5 U4.4@1425.2,2529.84 | length 1576.9
  Bottom w8: R15.2@250,1791.5 250,1955.1 824.74,2529.84 U4.4@1425.2,2529.84
OUT5: R16.2@170,1381.5 U4.5@1425.2,2549.53 | length 2041.3
  Bottom w8: R16.2@170,1381.5 170,1897.55 821.98,2549.53 U4.5@1425.2,2549.53
OUT6: R17.2@250,981.5 U4.6@1425.2,2569.21 | length 2568.8
  Bottom w8: R17.2@250,981.5 168.5,981.5 139.43,1010.57 139.43,1889.43 819.21,2569.21 U4.6@1425.2,2569.21
OUT7: R18.2@500,621.5 U4.7@1450.79,2594.8 | length 3103.7
  Bottom w8: R18.2@500,621.5 408.5,621.5 123.55,906.45 123.55,1901.1 807.54,2585.09 1390,2585.09 1399.72,2594.8 U4.7@1450.79,2594.8
OUT8: R19.2@780,431.5 U4.8@1470.47,2594.8 | length 3552.3
  Bottom w8: R19.2@780,431.5 571.83,431.5 107.68,895.65 107.68,1907.68 800.96,2600.96 1380,2600.96 1397.53,2618.49 1461.51,2618.49 1470.47,2609.53 U4.8@1470.47,2594.8
OUT9: R12.2@1220,331.5 U4.10@1509.84,2594.8 | length 3953.5
  Bottom w8: R12.2@1220,331.5 1268.5,380 1410,380 1453.06,336.94 1976.07,336.94 2528.2,889.07 2528.2,1921.68 1815.51,2634.36 1521.91,2634.36 1509.84,2622.29 U4.10@1509.84,2594.8
OUT10: R13.2@1840,431.5 U4.11@1529.53,2594.8 | length 3176.6
  Bottom w8: U4.11@1529.53,2594.8 1529.53,2609.53 1538.49,2618.49 1808.93,2618.49 2512.32,1915.1 2512.32,895.65 2048.17,431.5 R13.2@1840,431.5
OUT11: R14.2@2120,621.5 U4.12@1549.21,2594.8 | length 2729.4
  Bottom w8: U4.12@1550,2600 1804.97,2600 2496.45,1908.53 2496.45,906.45 2211.5,621.5 R14.2@2120,621.5
OUT12: R15.2@2370,981.5 U4.13@1574.8,2569.21 | length 2177.3
  Bottom w8: R15.2@2370,981.5 2421.5,981.5 2480.57,1040.57 2480.57,1901.54
  Bottom w10: U4.13@1574.8,2569.21 1811.9,2569.21 2479.57,1901.54
OUT13: R16.2@2450,1381.5 U4.14@1574.8,2549.53 | length 1666.2
  Bottom w10: U4.14@1574.8,2549.53 1806.31,2549.53 2450,1905.83 R16.2@2450,1381.5
OUT14: R17.2@2370,1791.5 U4.15@1574.8,2529.84 | length 1200.1
  Bottom w10: U4.15@1574.8,2529.84 1800.71,2529.84 2370,1960.56 R17.2@2370,1791.5
OUT15: R18.2@2120,2141.5 U4.16@1574.8,2510.16 | length 723.5
  Bottom w10: U4.16@1574.8,2510.16 1795.12,2510.16 2120,2185.28 R18.2@2120,2141.5
OUT16: R19.2@1840,2331.5 U4.17@1574.8,2490.47 | length 394.6
  Bottom w10: U4.17@1574.8,2490.47 1789.53,2490.47 1840,2440 R19.2@1840,2331.5
RESET: U4.12@1849.21,1245.2 U6.2 U6.12 | length 1438
  Top w10: U6.12 905.59,1064.41 930,1040 970,1040 990.24,1060.24 990.24,1080 ; U6.2 931.18,1278.82 990.24,1219.76 990.24,1080 ; v1(1030,1080) 990.24,1080 ; v1(1650,1060) 1708.84,1060 1849.21,1200.37 U4.12@1849.21,1245.2
  Bottom w10: v1(1030,1080) 1060,1110 1600,1110 v1(1650,1060)
SCL: P1.2 R7.1 U4.19 | length 2087.1
  Top w10: P1.2 1452.4,1757.6 1676.02,1757.6 R7.1 ; U4.19@1849.21,1394.8 1850,1395.59 1850,1410.86 1869.14,1430 v1(1950,1430)
  Bottom w10: P1.2 1410,1850 1310,1950 1310,2254.72 1367.4,2312.13 1507.4,2312.13 1549.21,2353.94 U4.19@1549.21,2445.2 ; P1.2@1425,1785 1452.4,1757.6 1705.96,1757.6 1950,1513.56 v1(1950,1430)
SDA: P1.3 R8.1 U4.20 | length 2071.8
  Top w10: P1.3 1376.38,1733.62 1620,1733.62 R8.1 ; U4.20@1829.53,1394.8 1829.53,1415.66 v1@1900,1486.14
  Bottom w10: U4.20@1529.53,2445.2 1529.53,2359.53 1500,2330 1360,2330 1290,2260 1290,1820 P1.3 1376.38,1733.62 1596.38,1733.62 1850,1480 v1(1900,1480)
SWITCH: C3.1 R4.1 U4.11@1829.53,1245.2 | length 851.8
  Top w10: R4.1 1466.38,1496.38 1480,1510 1480,1530 1491.5,1541.5 C3.1 v1@1608.5,1541.5 ; v1(1690,1120) 1743.56,1120 1829.53,1205.97 U4.11@1829.53,1245.2
  Bottom w10: v1(1610,1540) 1697.87,1452.13 v1@1697.87,1127.87
pads on no net: U4.22@1490.16,2445.2 U5.1 U8.1 U9.1
copper on no net:
  other v2: 1230,650 1250,650 1270,650 1290,650 1310,650 1330,650 1350,650 1370,650 1390,650 610,1270 2010,1270 610,1290 2010,1290 610,1310 2010,1310 610,1330 2010,1330 610,1350 2010,1350 610,1370 2010,1370 610,1390 2010,1390 610,1410 2010,1410 610,1430 2010,1430 1230,2050 1250,2050 1270,2050 1350,2050 1370,2050 1390,2050

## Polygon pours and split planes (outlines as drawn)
GND on Ground (split plane): 2619.9,20.1 20.1,20.1 20.1,3139.9 2619.9,3139.9
3V3 on Power (split plane): 2619.9,20.1 20.1,20.1 20.1,3139.9 2619.9,3139.9

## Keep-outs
Keep-Out Layer:
  text ".Layer_Name" at 577,-858.49 h60

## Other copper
Top:
  text "©" at 90,120 h105
  text ".CopyrightYear" at 210,120 h60
  text "TI" at 486,120 h60
  text ".Layer_Name" at 577,-858.49 h60
Bottom:
  text ".Layer_Name" at 577,-858.49 h60

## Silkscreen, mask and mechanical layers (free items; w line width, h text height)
Top Overlay:
  lines w8: 1480,1870 1480,1970
  text "GND" at 1130,1870 h40 r90
  text "3V3" at 1230,1870 h40 r90
  text "SDA" at 1330,1870 h40 r90
  text "SCL" at 1430,1870 h40 r90
  text "INT" at 1530,1870 h40 r90
  text "Discrete Logic" at 1030,940 h40
  text "Rotary Quadrature Decoder" at 830,870 h40
  text "with I2C Interface" at 970,790 h40
  text ".PRJ_Number" at 1140,120 h60
  text ".PCB_Rev" at 1740,120 h60
  text ".Layer_Name" at 577,-858.49 h60
Bottom Overlay:
  lines w6: 1160,2830 1260,2830
  text "CW" at 530,2780 h40
  text "INT" at 1260,2780 h40
  text "CCW" at 1980,2780 h40
  text "Texas Instruments" at 1630,950 h40
  text "Standard Linear" at 1580,850 h40
  text "and Logic" at 1480,750 h40
  text ".Layer_Name" at 577,-858.49 h60
Top Paste:
  text ".Layer_Name" at 577,-858.49 h60
Bottom Paste:
  text ".Layer_Name" at 577,-858.49 h60
Top Solder:
  text ".Layer_Name" at 577,-858.49 h60
  text ".Layer_Name" at 577,-858.49 h60
Bottom Solder:
  text ".Layer_Name" at 577,-858.49 h60
Drill Guide:
  text ".Layer_Name" at 577,-858.49 h60
Mechanical 1:
  lines w10: 607.85,1447.38 409.76,1447.38 cw(c1310,1349.53) 1210,2249.53 1210,2049.53 ccw(c1310,1349.53) 610,1449.53 ; 608.89,1248.42 410.12,1248.42 ccw(c1310,1349.53) 1210,449.53 1210,649.53 cw(c1310,1349.53) 610,1249.53 ; 2010,1249.53 cw(c1310,1349.53) 1410,649.53 1410,449.53 ccw(c1310,1349.53) 2210,1249.53 ; 2010,1250 2210,1250 ; 2208.62,1448.15 2010.19,1448.15 ccw(c1310,1349.53) 1410,2049.53 1410,2249.53 cw(c1310,1349.53) 2210,1449.53 ; 0,0 0,3160 2640,3160 2640,0 2350,0 0,0
  text ".Layer_Name" at 577,-858.49 h60
Mechanical 2:
  circle w10: c1310,1350 r1050
  rectangle: 125,-400 500,-275
  rectangle: 0,-275 125,-150
  lines w7: 0,-275 1000,-275 ; 125,-400 125,-150 ; 250,-400 250,-150 ; 500,-400 500,-150 ; 750,-400 750,-150 ; 0,-400 0,-150 1000,-150 1000,-400 0,-400
  text ".Layer_Name" at 577,-858.49 h60
Mechanical 3:
  text ".Layer_Name" at 577,-858.49 h60
Mechanical 4:
  text ".Layer_Name" at 577,-858.49 h60
Mechanical 5:
  lines w10: -292,-930.17 6308,-930.17 ; -292,-726.83 6310,-726.83 ; -292,-523.5 -292,-1133.5 3713,-1133.5 6310,-1133.5 6310,-523.5 -291.5,-523.5 -291.5,-1133.5 1284,-1133.5 ; 2173,-1133.5 2173,-523.5 ; 3440,-726.83 3440,-523.5 ; 4280,-726.83 4280,-523.5 ; 4902,-1140 4902,-937.17
  text "COMPONENTS MARKED 'DNP' SHOULD NOT BE POPULATED." at 1153.5,-318.5 h60
  text "ASSEMBLY VARIANT:" at 1153,-434 h60
  text ".VariantName" at 2189,-434 h60
  text "PCB VIEWED FROM TOP SIDE" at -228.5,-655.67 h60
  text "BOARD #:" at 2248,-655.67 h60
  text ".PRJ_Number" at 2793.5,-655.67 h60
  text "REV:" at 3638,-655.67 h60
  text ".PCB_Rev" at 3929.5,-655.67 h60
  text "SVN REV:" at 4476,-655.67 h60
  text ".VersionControl_RevNumber" at 4982,-655.67 h60
  text "TID #:" at 2248,-859 h60
  text ".TID" at 2793.5,-859 h60
  text "PLOT NAME =" at -228.5,-1064.34 h60
  text ".plot_File_Name" at 577,-1064.34 h60
  text "GENERATED    :" at 2250,-1064.34 h60
  text ".Print_Date" at 3119.5,-1064.34 h60
  text ".Print_Time" at 3848.5,-1064.34 h60
  text "TEXAS INSTRUMENTS" at 5113,-1064.34 h60
Mechanical 6:
  lines w10: -292.5,-727.33 6309.5,-727.33 ; -290.5,-930.67 6309.5,-930.67 ; 1115.5,-1140.5 1115.5,-937.67 ; 1737.5,-727.33 1737.5,-524 ; 2577.5,-727.33 2577.5,-524 ; 3844.5,-1134 3844.5,-524 ; 4733.5,-1134 6309,-1134 6309,-524 -292.5,-524 -292.5,-1134 2304.5,-1134 6309.5,-1134 6309.5,-524
  text "COMPONENTS MARKED 'DNP' SHOULD NOT BE POPULATED." at 6102,-318 h60
  text ".VariantName" at 5058,-434 h60
  text "ASSEMBLY VARIANT:" at 6097,-434 h60
  text ".VersionControl_RevNumber" at 1035.5,-656.17 h60
  text "SVN REV:" at 1541.5,-656.17 h60
  text ".PCB_Rev" at 2088,-656.17 h60
  text "REV:" at 2379.5,-656.17 h60
  text ".PRJ_Number" at 3224,-656.17 h60
  text "BOARD #:" at 3769.5,-656.17 h60
  text "PCB VIEWED FROM BOTTOM SIDE" at 6246,-656.17 h60
  text ".TID" at 3224,-859.5 h60
  text "TID #:" at 3769.5,-859.5 h60
  text "TEXAS INSTRUMENTS" at 904.5,-1064.84 h60
  text ".Print_Time" at 2169,-1064.84 h60
  text ".Print_Date" at 2898,-1064.84 h60
  text "GENERATED    :" at 3767.5,-1064.84 h60
  text ".plot_File_Name" at 5440.5,-1064.84 h60
  text "PLOT NAME =" at 6246,-1064.84 h60
Mechanical 9:
  drawing of 57 lines, arcs and shapes, not listed
  text "1" at 739.84,8036.5 h70
  text "2" at 3235.5,8036.5 h70
  text "3" at 5724.84,8036.5 h70
  text "4" at 8231.51,8036.5 h70
  text "5" at 10730.5,8036.5 h70
  text "6" at 13235.5,8036.5 h70
  text "A" at -416.5,6893.5 h70
  text "A" at 14383.5,6893.5 h70
  text "B" at -416.5,4513.5 h70
  text "B" at 14383.5,4513.5 h70
  text "C" at -416.5,2138.5 h70
  text "C" at 14383.5,2138.5 h70
  text "PROJECT TITLE:" at 11343.5,277.5 h45
  text ".PRJ_Title" at 11393.5,144.17 h70
  text "DESIGNED FOR:" at 11343.5,-23.5 h45
  text ".PRJ_Customer" at 11393.5,-163.5 h70
  text "D" at -416.5,-231.5 h70
  text "D" at 14383.5,-231.5 h70
  text "FILE NAME:" at 11343.5,-323.5 h45
  text ".PCB_File_Name_No_Path" at 11393.5,-443.5 h70
  text "Texas Instruments (TI) and/or its licensors do not warrant the accuracy or completeness of this specification" at 6374,-605.34 h45
  text "ENGINEER:" at 11343.5,-613.5 h45
  text "LAYOUT BY:" at 12848.5,-613.5 h45
  text "or any information contained therein. TI and/or its licensors do not warrant that this design will meet" at 6329.01,-718 h45
  text ".PRJ_Engineer" at 11393.5,-768.49 h70
  text ".PCB_Layout" at 12899,-768.49 h70
  text "the specifications, will be suitable for your application or fit for any particular purpose, or will operate in" at 6329.01,-830.67 h45
  text ".Layer_Name" at 577,-858.49 h60
  text "ALTIUM DESIGNER VERSION:" at 12848.5,-923.5 h45
  text "an implementation. TI and/or its licensors do not warrant that the design is production worthy. You should" at 6329.01,-943.33 h45
  text "completely validate and test your design implementation to confirm the system functionality for your application." at 6374,-1056 h45
  text ".print_Scale" at 11393.5,-1056.83 h70
  text ".Application_BuildNumber" at 12899,-1056.83 h70
  text "1" at 739.84,-1263.5 h70
  text "2" at 3235.5,-1263.5 h70
  text "3" at 5724.84,-1263.5 h70
  text "4" at 8231.51,-1263.5 h70
  text "5" at 10730.5,-1263.5 h70
  text "6" at 13235.5,-1263.5 h70
Mechanical 10:
  drawing of 185 lines, arcs and shapes, not listed
  text "DESIGN INFORMATION" at 12381.02,5910 h60
  text "MIN. TRACK WIDTH:" at 11736.46,5730 h60
  text "8" at 12832.7,5730 h60
  text "MIL" at 12987.46,5730 h60
  text "MIN. CLEARANCE:" at 11736.46,5598 h60
  text "0.2" at 12772.7,5598 h60
  text "mm" at 12987.46,5598 h60
  text "MIN. VIA PAD SIZE:" at 11736.46,5466 h60
  text "24" at 12802.71,5466 h60
  text "MIL" at 12987.46,5466 h60
  text "0.05mm (2MIL)" at 12431.46,5324.29 h60
  text "MINIMUM ANNULAR RING" at 11407.23,5320 h60
  text "EXTERNAL" at 13139.46,5320 h60
  text "PER" at 11607.23,5202 h60
  text "IPC-D-275 CLASS 2 LEVEL C" at 11827.23,5202 h60
  text "MIL, HOLES" at 13315.46,5089.71 h60
  text "+/-" at 12923,5089 h60
  text "+/-" at 13777,5089 h60
  text "REGISTRATION TOLERANCES:" at 11407.23,5084 h60
  text "METAL" at 12607,5084 h60
  text "5" at 13183.2,5084 h60
  text "3" at 14016.2,5084 h60
  text "MIL" at 14132.46,5084 h60
  text "MATERIAL:" at 11332.46,4874.54 h60
  text "FR-4 High Tg" at 12318.9,4734.21 h60
  text "FR-408" at 11753.46,4725.64 h60
  text "X" at 12165.46,4725.64 h60
  text "OTHER" at 13241.46,4725.64 h60
  text "62 MIL (1.6mm) +/-10%" at 12073.56,4562.92 h60
  text "THICKNESS:" at 11407.23,4558.64 h60
  text "X" at 11945.4,4558.64 h60
  text "OTHER" at 13358.46,4558.64 h60
  text "TOLERANCE:" at 11407.23,4400.64 h60
  text "X" at 12246.53,4400.64 h60
  text "ANSI IPC-6012 TYPE 3 CLASS 2" at 12433.48,4400.64 h60
  text "OTHER +/-" at 12433.46,4244.64 h60
  text "BOW & TWIST:" at 11407.23,4087.64 h60
  text "X" at 12246.53,4087.64 h60
  text "ANSI IPC-6012 TYPE 3 CLASS 2" at 12433.48,4087.64 h60
  text "OTHER +/-" at 12433.46,3929.13 h60
  text "DRILLING:" at 11332.46,3790.64 h60
  text "REFERENCE:" at 11407.23,3673.64 h60
  text "X" at 12055.46,3673.64 h60
  text "AS SHOWN" at 12242.46,3673.64 h60
  text "X" at 12956.46,3673.64 h60
  text "NC_DRILL FILES" at 13093.46,3673.64 h60
  text "PTH MIN COPPER THICKNESS:" at 11407.23,3515.64 h60
  text "X" at 12757.46,3515.64 h60
  text "1MIL" at 12894.46,3515.64 h60
  text "OTHER" at 13391.46,3515.64 h60
  text "BOARD FINISH:" at 11332.46,3356.64 h60
  text "SILKSCREEN:" at 11487.68,3238.64 h60
  text "X" at 12436.46,3238.64 h60
  text "TOP" at 12562.46,3238.64 h60
  text "X" at 12946.46,3238.64 h60
  text "BOTTOM" at 13073.46,3238.64 h60
  text "SILKSCREEN COLOR:" at 11487.68,3071.64 h60
  text "X" at 12435.42,3071.64 h60
  text "WHITE" at 12562.46,3071.64 h60
  text "OTHER" at 13073.46,3071.64 h60
  text "SOLDER RESIST COLOR:" at 11487.68,2901.64 h60
  text "X" at 12055.42,2742.44 h60
  text "GREEN" at 12182.46,2742.44 h60
  text "BLUE" at 12773.46,2742.44 h60
  text "OTHER" at 13311.46,2742.44 h60
  text "IMMERSION GOLD (ENIG)" at 12393.46,2553.92 h60
  text "ENEPIG" at 13731,2550.64 h60
  text "SURFACE FINISH:" at 11332.46,2549.64 h60
  text "X" at 12206.51,2549.64 h60
  text "IMM. TIN/SILVER OR EQUIV" at 11662,2392.64 h60
  text "OTHER" at 13093.46,2392.64 h60
  text "ARRAY/PANEL:" at 11332.46,2213.64 h60
  text "CUT AND TRIM PER MECH LAYER 1" at 12393.46,2209.35 h60
  text "N.C. ROUTE" at 12393.46,2057.64 h60
  text "X" at 13072.46,2057.64 h60
  text "V. SCORE" at 13259.46,2057.64 h60
  text "CERTIFICATION:" at 11332.46,1920.64 h60
  text "MATERIALS AND WORKMANSHIP FOR ALL PCBS" at 12057.46,1920.64 h60
  text "TO MEET OR EXCEED THE REQUIREMENTS OF:" at 12057.46,1822.64 h60
  text "X" at 11683.96,1686.13 h60
  text "ANSI IPC-A-600F CLASS ->" at 11822.96,1686.13 h60
  text "X" at 13462.02,1686.13 h60
  text "2" at 13580.96,1686.14 h60
  text "1" at 13265.96,1684.64 h60
  text "3" at 13934.96,1684.64 h60
  text "X" at 11686.02,1526.64 h60
  text "UL 94V-0" at 11822.96,1526.64 h60
  text "X" at 12498.02,1526.64 h60
  text "RoHS" at 12634.96,1526.64 h60
  text "OTHER" at 13279.36,1526.64 h60
  text "PER ORDER" at 13676.42,1526.64 h60
  text "ADDITIONAL REQUIREMENTS:" at 11332.46,1385.64 h60
  text "MICROSECTION:" at 11407.23,1270.64 h60
  text "YES" at 12312.96,1270.64 h60
  text "REQUIRED" at 13174.46,1114.49 h60
  text "BARE BOARD ELEC. TEST:" at 11407.23,1111.64 h60
  text "NONE" at 12712.96,1111.64 h60
  text "X" at 13047.46,1111.64 h60
  text "PER ORDER" at 13766.46,1111.64 h60
  text "MANUFACTURER'S UL:" at 11407.23,954.64 h60
  text "RAIL" at 12572.96,950.35 h60
  text "METAL" at 13064.77,950.35 h60
  text "X" at 13440,950 h60
  text "SILK" at 13576.46,950.35 h60
  text ".Layer_Name" at 577,-858.49 h60
Mechanical 11:
  lines w10: -292,-930.17 6308,-930.17 ; -292,-726.83 6310,-726.83 ; -292,-523.5 -292,-1133.5 3713,-1133.5 6310,-1133.5 6310,-523.5 -291.5,-523.5 -291.5,-1133.5 1284,-1133.5 ; 2173,-1133.5 2173,-523.5 ; 3440,-726.83 3440,-523.5 ; 4280,-726.83 4280,-523.5 ; 4902,-1140 4902,-937.17
  text "ALL ARTWORK VIEWED FROM TOP SIDE" at -228.5,-655.67 h60
  text "BOARD #:" at 2248,-655.67 h60
  text ".PRJ_Number" at 2793.5,-655.67 h60
  text "REV:" at 3638,-655.67 h60
  text ".PCB_Rev" at 3929.5,-655.67 h60
  text "SVN REV:" at 4476,-655.67 h60
  text ".VersionControl_RevNumber" at 4982,-655.67 h60
  text "LAYER NAME =" at -228.5,-858.49 h60
  text "TID #:" at 2248,-859 h60
  text ".TID" at 2793.5,-859 h60
  text "PLOT NAME =" at -228.5,-1064.34 h60
  text ".plot_File_Name" at 577,-1064.34 h60
  text "GENERATED    :" at 2250,-1064.34 h60
  text ".Print_Date" at 3119.5,-1064.34 h60
  text ".Print_Time" at 3848.5,-1064.34 h60
  text "TEXAS INSTRUMENTS" at 5113,-1064.34 h60
Mechanical 12:
  drawing of 191 lines, arcs and shapes, not listed
  text "Layer" at 9790.58,7830 h60
  text "Name" at 10200.49,7830 h60
  text "Material" at 11130.23,7830 h60
  text "Thickness" at 11990,7830 h60
  text "Constant" at 12639.84,7830 h60
  text "Board Layer Stack" at 13209.7,7830 h60
  text "1" at 9790.58,7710 h60
  text "Top Overlay" at 10200.49,7710 h60
  text "2" at 9790.58,7590 h60
  text "Top Solder" at 10200.49,7590 h60
  text "Solder Resist" at 11130.23,7590 h60
  text "0.40mil" at 11990,7590 h60
  text "3.5" at 12639.84,7590 h60
  text "3" at 9790.58,7470 h60
  text "Top Layer" at 10200.49,7470 h60
  text "Copper" at 11130.23,7470 h60
  text "1.40mil" at 11990,7470 h60
  text "4" at 9790.58,7350 h60
  text "Dielectric1" at 10200.49,7350 h60
  text "FR-4" at 11130.23,7350 h60
  text "59.20mil" at 11990,7350 h60
  text "4.8" at 12639.84,7350 h60
  text "5" at 9790.58,7230 h60
  text "Bottom Layer" at 10200.49,7230 h60
  text "Copper" at 11130.23,7230 h60
  text "1.40mil" at 11990,7230 h60
  text "6" at 9790.58,7110 h60
  text "Bottom Solder" at 10200.49,7110 h60
  text "Solder Resist" at 11130.23,7110 h60
  text "0.40mil" at 11990,7110 h60
  text "3.5" at 12639.84,7110 h60
  text "7" at 9790.58,6990 h60
  text "Bottom Overlay" at 10200.49,6990 h60
  text ".Layer_Name" at 577,-858.49 h60
Mechanical 13:
  text ".Layer_Name" at 577,-858.49 h60
Mechanical 14:
  text ".Layer_Name" at 577,-858.49 h60
Mechanical 15:
  text ".Layer_Name" at 577,-858.49 h60
Mechanical 16:
  text ".Layer_Name" at 577,-858.49 h60
Drill Drawing:
  circle w1: c5557.8,3259.18 r20.74
  lines w1: 5537.05,2616.19 5557.8,2626.56 5578.54,2616.19 5568.17,2636.93 5578.54,2657.67 5557.8,2647.3 5537.05,2657.67 5547.42,2636.93 5537.05,2616.19 ; 5537.05,2740.64 5578.54,2740.64 5578.54,2782.12 5537.05,2782.12 5537.05,2740.64 ; 5537.05,2875.46 5547.42,2875.46 5547.42,2865.09 5568.17,2865.09 5568.17,2875.46 5578.54,2875.46 5578.54,2896.2 5568.17,2896.2 5568.17,2906.57 5547.42,2906.57 5547.42,2896.2 5537.05,2896.2 5537.05,2875.46 ; 5537.05,2999.91 5547.42,2999.91 5557.8,2989.53 5568.17,2999.91 5578.54,2999.91 5568.17,3010.28 5578.54,3020.65 5568.17,3020.65 5557.8,3031.02 5547.42,3020.65 5537.05,3020.65 5547.42,3010.28 5537.05,2999.91 ; 5537.05,3155.47 5578.54,3155.47 5557.8,3113.98 5537.05,3155.47
  lines w12: 5480,2578.85 7509.36,2578.85 ; 5480,3325.55 7509.36,3325.55 ; 5828.16,2454.4 5828.16,3450 ; 6170.27,2454.4 6170.27,3450 ; 6817.27,2454.4 6817.27,3450 ; 7086.62,2454.4 7086.62,3450 ; 5480,2454.4 7509.36,2454.4 7509.36,3450 5480,3450 5480,2454.4
  text "Symbol" at 5554.67,3362.89 h72
  text "Quantity" at 5865.5,3362.89 h72
  text "Finished Hole Size" at 6207.6,3362.89 h72
  text "Plated" at 6854.6,3362.89 h72
  text "Hole Type" at 7123.95,3362.89 h72
  text "10" at 5865.5,3238.44 h60
  text "7.87mil (0.200mm)" at 6207.6,3238.44 h60
  text "PTH" at 6854.6,3238.44 h60
  text "Round" at 7123.95,3238.44 h60
  text "33" at 5865.5,3113.98 h60
  text "13.00mil (0.330mm)" at 6207.6,3113.98 h60
  text "PTH" at 6854.6,3113.98 h60
  text "Round" at 7123.95,3113.98 h60
  text "52" at 5865.5,2989.53 h60
  text "28.00mil (0.711mm)" at 6207.6,2989.53 h60
  text "PTH" at 6854.6,2989.53 h60
  text "Round" at 7123.95,2989.53 h60
  text "5" at 5865.5,2865.09 h60
  text "33.46mil (0.850mm)" at 6207.6,2865.09 h60
  text "PTH" at 6854.6,2865.09 h60
  text "Round" at 7123.95,2865.09 h60
  text "5" at 5865.5,2740.64 h60
  text "39.37mil (1.000mm)" at 6207.6,2740.64 h60
  text "PTH" at 6854.6,2740.64 h60
  text "Round" at 7123.95,2740.64 h60
  text "2" at 5865.5,2616.19 h60
  text "78.74mil (2.000mm)" at 6207.6,2616.19 h60
  text "PTH" at 6854.6,2616.19 h60
  text "Slot" at 7123.95,2616.19 h60
  text "107 Total" at 5865.5,2491.74 h60
  text ".Layer_Name" at 577,-858.49 h60

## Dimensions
0,-400 to 1000,-400 on Mechanical 2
